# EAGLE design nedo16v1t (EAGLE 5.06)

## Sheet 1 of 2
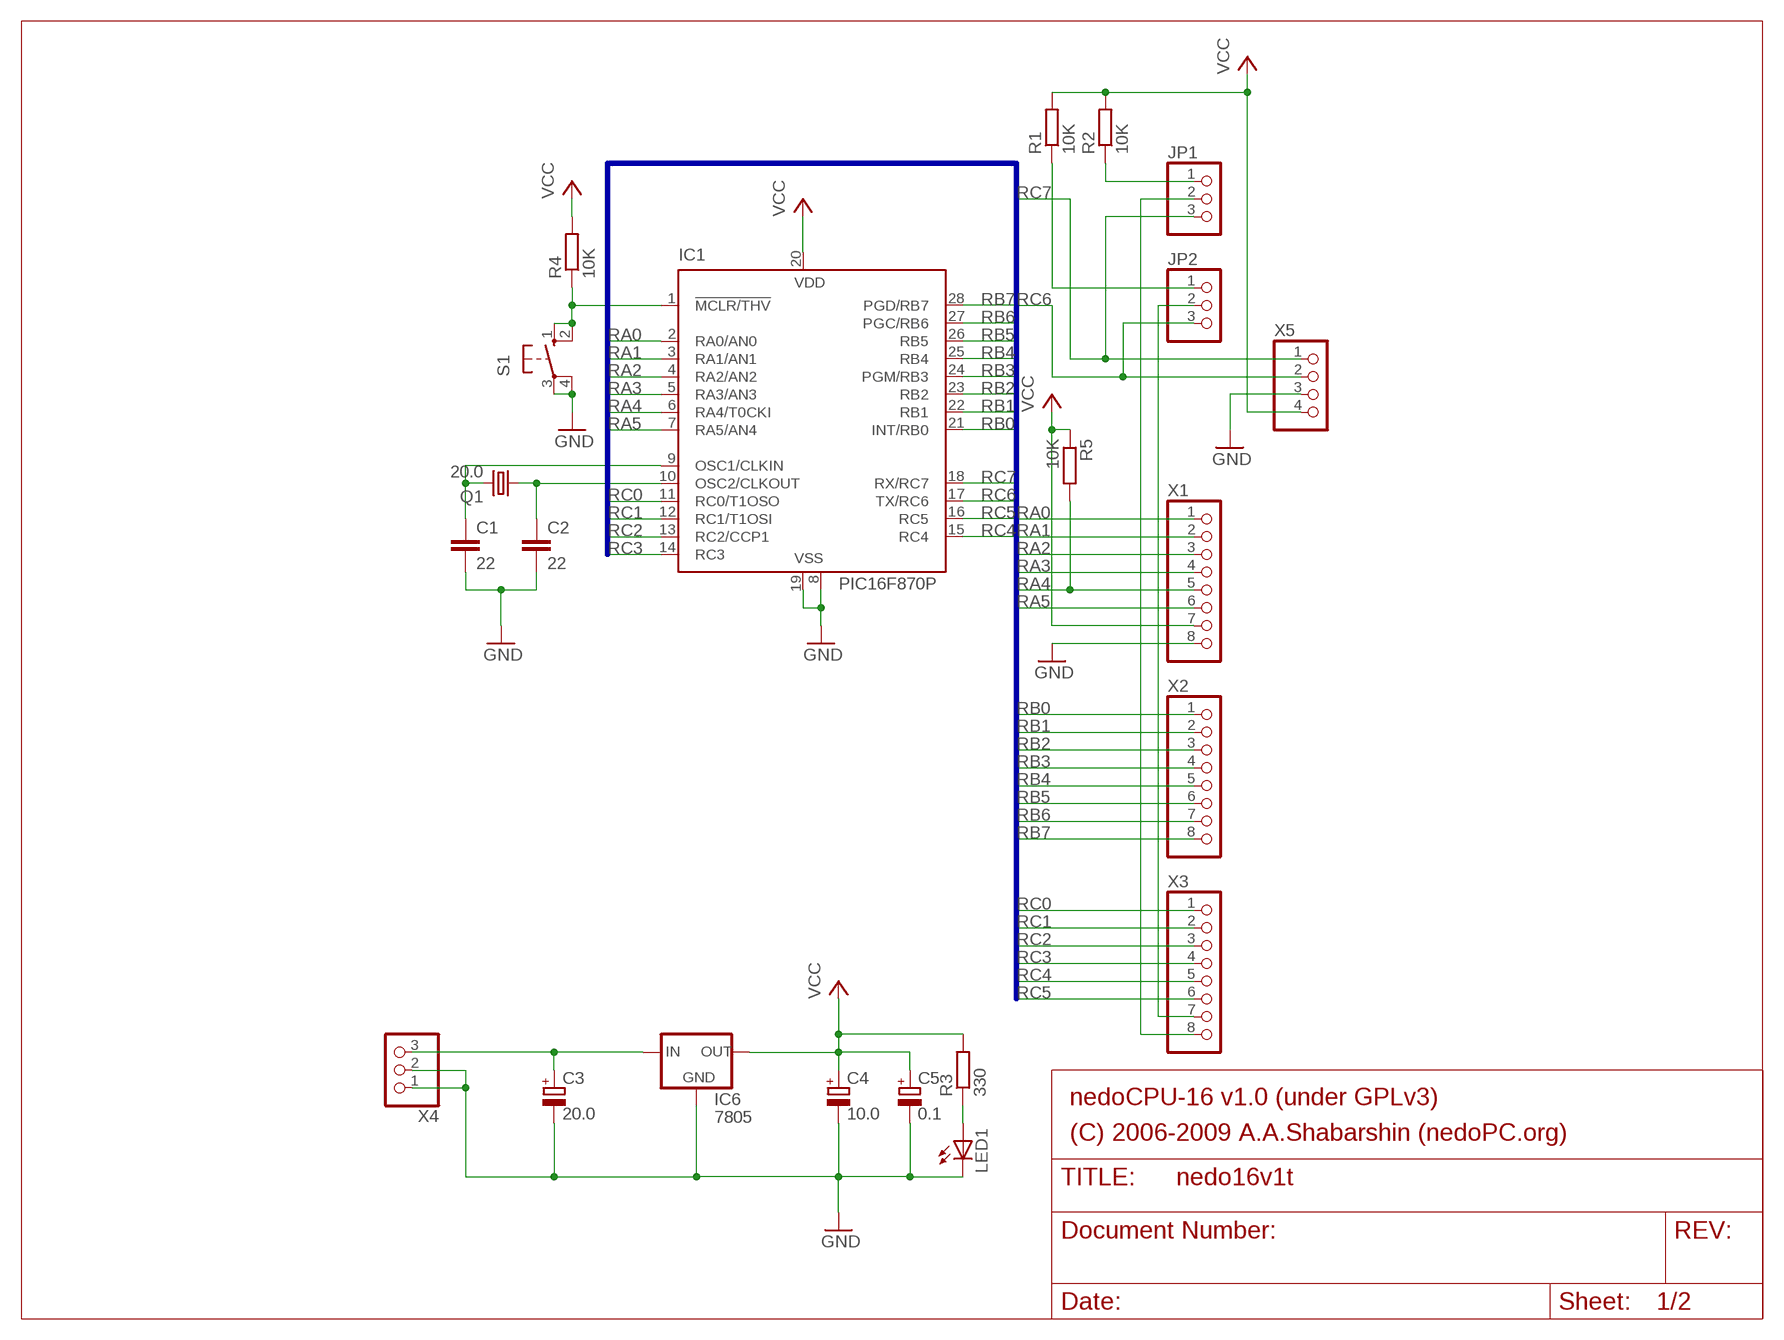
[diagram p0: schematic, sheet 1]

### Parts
C1  22  C-EU025-024X044  [C025-024X044]
C2  22  C-EU025-024X044  [C025-024X044]
C3  20.0  CPOL-EUE5-6  [E5-6]
C4  10.0  CPOL-EUE2.5-6  [E2,5-6]
C5  0.1  CPOL-EUB45181A  [B45181A]
IC1  PIC16F870P  [DIL28-3]
IC6  7805  78XXS  [78XXS]
JP1  PINHD-1X3  [1X03]
JP2  PINHD-1X3  [1X03]
LED1  LED5MM  [LED5MM]
Q1  20.0  CRYSTALHC49U-V  [HC49U-V]
R1  10K  R-EU_0204/7  [0204/7]
R2  10K  R-EU_0204/7  [0204/7]
R3  330  R-EU_0204/7  [0204/7]
R4  10K  R-EU_0204/7  [0204/7]
R5  10K  R-EU_0207/7  [0207/7]
S1  10-XX  [B3F-10XX]
X1  PINHD-1X8  [1X08]
X2  PINHD-1X8  [1X08]
X3  PINHD-1X8  [1X08]
X4  PINHD-1X3  [1X03]
X5  PINHD-1X4  [1X04]

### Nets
GND: C1.2 C2.2 C3.- C4.- C5.- IC1.8(VSS) IC1.19(VSS) IC6.GND LED1.K(C) S1.3(P) S1.4(P1) X1.8 X4.1 X4.2 X5.3 ; also sheet 2
N$3: IC1.1(!MCLR/THV) R4.1 S1.1(S) S1.2(S1)
N$4: JP1.1 R2.1
N$5: JP2.1 R1.1
N$7: LED1.A R3.1
N$10: C2.1 IC1.10(OSC2/CLKOUT) Q1.1
N$14: C3.+ IC6.IN X4.3
N$16: C1.1 IC1.9(OSC1/CLKIN) Q1.2
RA0: IC1.2(RA0/AN0) X1.1 ; also sheet 2
RA1: IC1.3(RA1/AN1) X1.2 ; also sheet 2
RA2: IC1.4(RA2/AN2) X1.3 ; also sheet 2
RA3: IC1.5(RA3/AN3) X1.4 ; also sheet 2
RA4: IC1.6(RA4/T0CKI) R5.2 X1.5 ; also sheet 2
RA5: IC1.7(RA5/AN4) X1.6 ; also sheet 2
RB0: IC1.21(INT/RB0) X2.1 ; also sheet 2
RB1: IC1.22(RB1) X2.2 ; also sheet 2
RB2: IC1.23(RB2) X2.3 ; also sheet 2
RB3: IC1.24(PGM/RB3) X2.4 ; also sheet 2
RB4: IC1.25(RB4) X2.5 ; also sheet 2
RB5: IC1.26(RB5) X2.6 ; also sheet 2
RB6: IC1.27(PGC/RB6) X2.7 ; also sheet 2
RB7: IC1.28(PGD/RB7) X2.8 ; also sheet 2
RC0: IC1.11(RC0/T1OSO) X3.1 ; also sheet 2
RC1: IC1.12(RC1/T1OSI) X3.2 ; also sheet 2
RC2: IC1.13(RC2/CCP1) X3.3 ; also sheet 2
RC3: IC1.14(RC3) X3.4 ; also sheet 2
RC4: IC1.15(RC4) X3.5 ; also sheet 2
RC5: IC1.16(RC5) X3.6 ; also sheet 2
RC6: IC1.17(TX/RC6) JP2.3 X5.2
RC7: IC1.18(RX/RC7) JP1.3 X5.1
RX: JP1.2 X3.8 ; also sheet 2
TX: JP2.2 X3.7 ; also sheet 2
VCC: C4.+ C5.+ IC1.20(VDD) IC6.OUT R1.2 R2.2 R3.2 R4.2 R5.1 X1.7 X5.4 ; also sheet 2

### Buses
RA[0..5],RB[0..7],RC[0..7]

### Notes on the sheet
- nedoCPU-16 v1.0 (under GPLv3)
- (C) 2006-2009 A.A.Shabarshin (nedoPC.org)

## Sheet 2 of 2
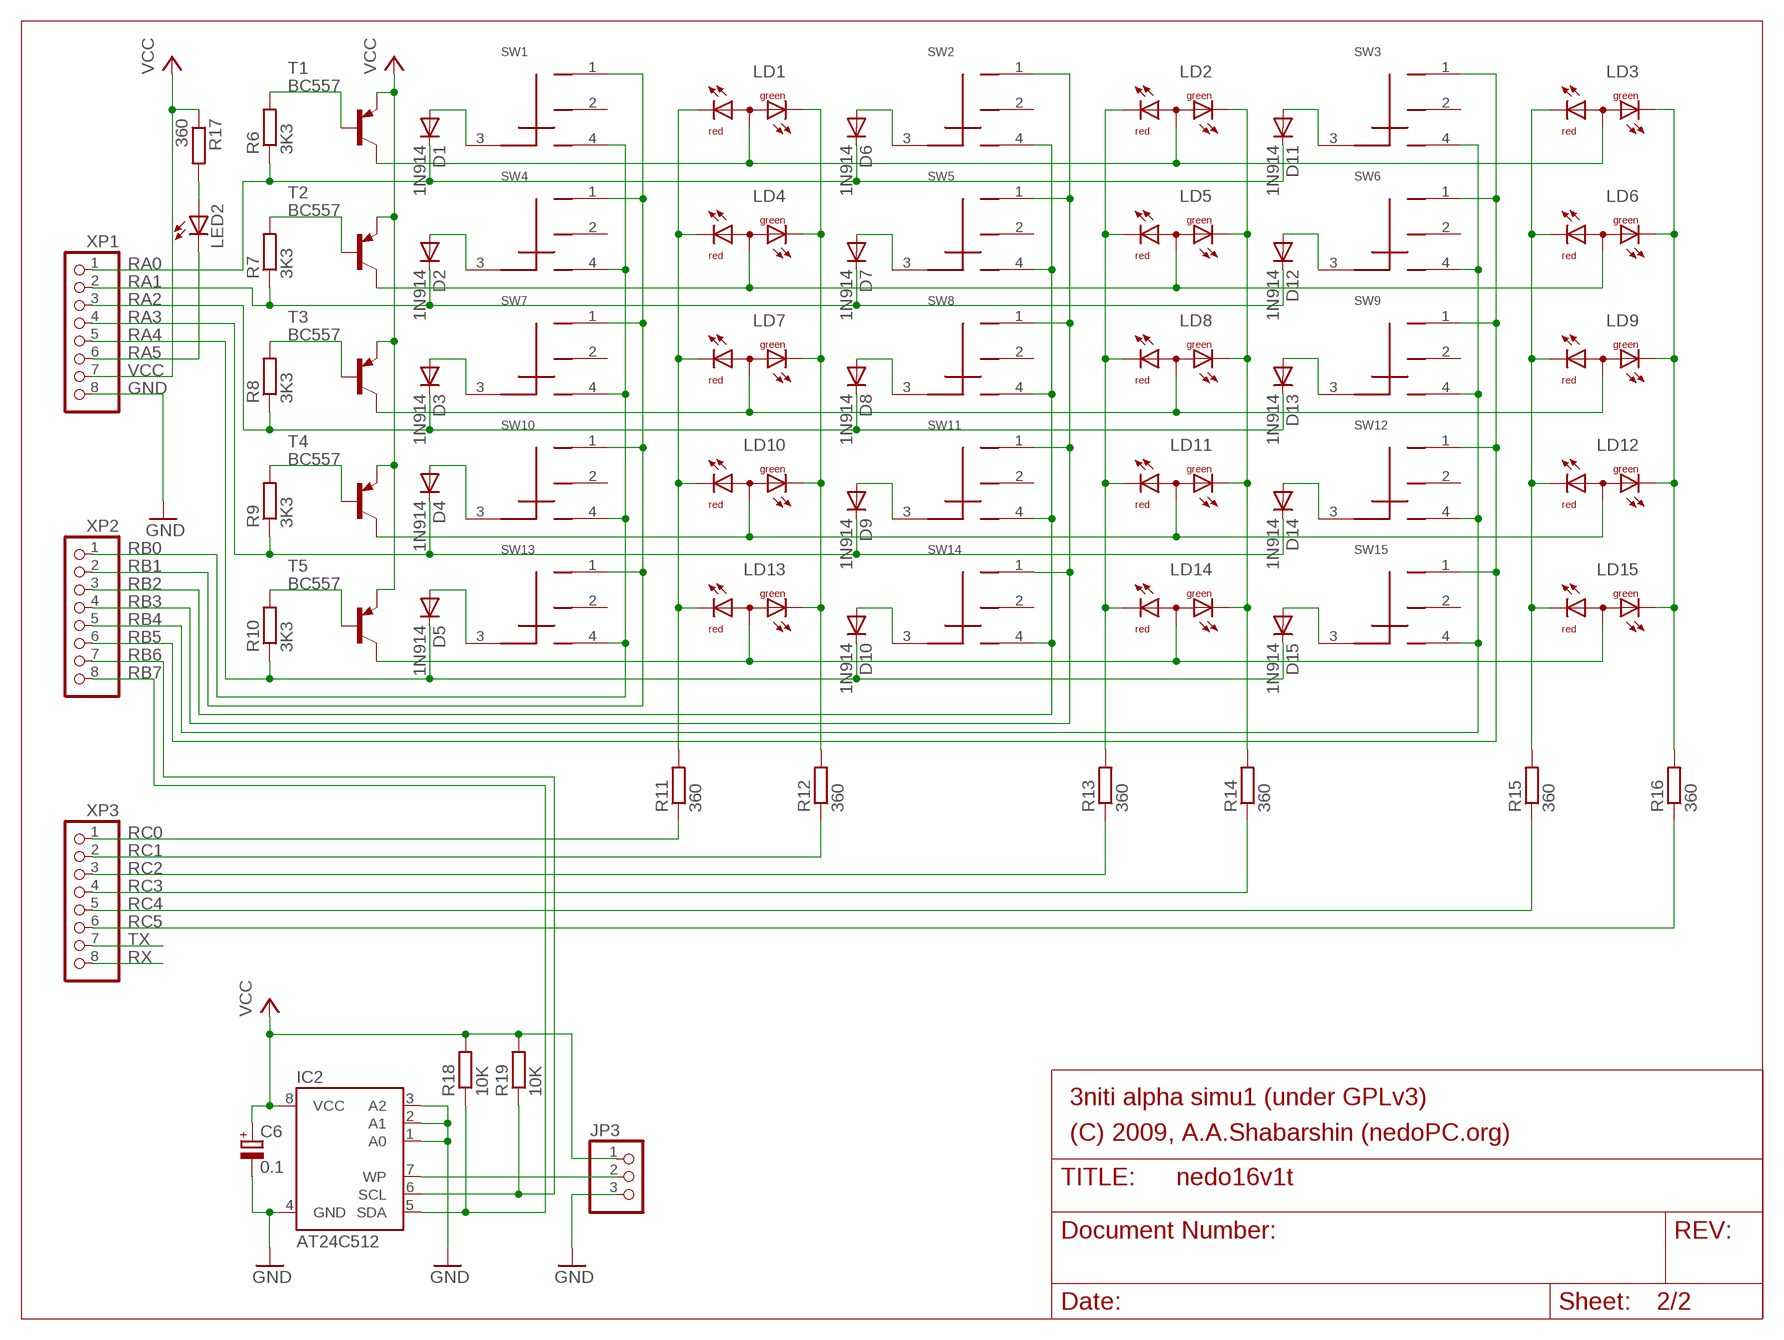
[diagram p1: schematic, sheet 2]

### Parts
C6  0.1  CPOL-EUB45181A  [B45181A]
D1  1N914  1N4148DO35-7  [DO35-7]
D2  1N914  1N4148DO35-7  [DO35-7]
D3  1N914  1N4148DO35-7  [DO35-7]
D4  1N914  1N4148DO35-7  [DO35-7]
D5  1N914  1N4148DO35-7  [DO35-7]
D6  1N914  1N4148DO35-7  [DO35-7]
D7  1N914  1N4148DO35-7  [DO35-7]
D8  1N914  1N4148DO35-7  [DO35-7]
D9  1N914  1N4148DO35-7  [DO35-7]
D10  1N914  1N4148DO35-7  [DO35-7]
D11  1N914  1N4148DO35-7  [DO35-7]
D12  1N914  1N4148DO35-7  [DO35-7]
D13  1N914  1N4148DO35-7  [DO35-7]
D14  1N914  1N4148DO35-7  [DO35-7]
D15  1N914  1N4148DO35-7  [DO35-7]
IC2  AT24C512  AT24CP  [DIL08]
JP3  PINHD-1X3  [1X03]
LD1  DUOLED-RG-A  [DUOLED-A-5MM]
LD2  DUOLED-RG-A  [DUOLED-A-5MM]
LD3  DUOLED-RG-A  [DUOLED-A-5MM]
LD4  DUOLED-RG-A  [DUOLED-A-5MM]
LD5  DUOLED-RG-A  [DUOLED-A-5MM]
LD6  DUOLED-RG-A  [DUOLED-A-5MM]
LD7  DUOLED-RG-A  [DUOLED-A-5MM]
LD8  DUOLED-RG-A  [DUOLED-A-5MM]
LD9  DUOLED-RG-A  [DUOLED-A-5MM]
LD10  DUOLED-RG-A  [DUOLED-A-5MM]
LD11  DUOLED-RG-A  [DUOLED-A-5MM]
LD12  DUOLED-RG-A  [DUOLED-A-5MM]
LD13  DUOLED-RG-A  [DUOLED-A-5MM]
LD14  DUOLED-RG-A  [DUOLED-A-5MM]
LD15  DUOLED-RG-A  [DUOLED-A-5MM]
LED2  LED3MM  [LED3MM]
R6  3K3  R-EU_0204/2V  [0204V]
R7  3K3  R-EU_0204/2V  [0204V]
R8  3K3  R-EU_0204/2V  [0204V]
R9  3K3  R-EU_0204/2V  [0204V]
R10  3K3  R-EU_0204/2V  [0204V]
R11  360  R-EU_0204/2V  [0204V]
R12  360  R-EU_0204/2V  [0204V]
R13  360  R-EU_0204/2V  [0204V]
R14  360  R-EU_0204/2V  [0204V]
R15  360  R-EU_0204/2V  [0204V]
R16  360  R-EU_0204/2V  [0204V]
R17  360  R-EU_0207/2V  [0207/2V]
R18  10K  R-EU_0207/2V  [0207/2V]
R19  10K  R-EU_0207/2V  [0207/2V]
SW1  SP3T  [SP3T]
SW2  SP3T  [SP3T]
SW3  SP3T  [SP3T]
SW4  SP3T  [SP3T]
SW5  SP3T  [SP3T]
SW6  SP3T  [SP3T]
SW7  SP3T  [SP3T]
SW8  SP3T  [SP3T]
SW9  SP3T  [SP3T]
SW10  SP3T  [SP3T]
SW11  SP3T  [SP3T]
SW12  SP3T  [SP3T]
SW13  SP3T  [SP3T]
SW14  SP3T  [SP3T]
SW15  SP3T  [SP3T]
T1  BC557  BC557A-PNP-TO92-EBC  [TO92-EBC]
T2  BC557  BC557A-PNP-TO92-EBC  [TO92-EBC]
T3  BC557  BC557A-PNP-TO92-EBC  [TO92-EBC]
T4  BC557  BC557A-PNP-TO92-EBC  [TO92-EBC]
T5  BC557  BC557A-PNP-TO92-EBC  [TO92-EBC]
XP1  PINHD-1X8  [1X08]
XP2  PINHD-1X8  [1X08]
XP3  PINHD-1X8  [1X08]

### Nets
GND: C6.- IC2.1(A0) IC2.2(A1) IC2.3(A2) IC2.4(GND) JP3.3 XP1.8 ; also sheet 1
N$1: LD1.CR LD4.CR LD7.CR LD10.CR LD13.CR R11.2
N$2: LD1.A LD2.A LD3.A T1.C
N$6: R6.2 T1.B
N$8: LD1.CX(CG) LD4.CX(CG) LD7.CX(CG) LD10.CX(CG) LD13.CX(CG) R12.2
N$9: LD4.A LD5.A LD6.A T2.C
N$11: R7.2 T2.B
N$12: R8.2 T3.B
N$13: R9.2 T4.B
N$15: R10.2 T5.B
N$17: LD7.A LD8.A LD9.A T3.C
N$18: LD10.A LD11.A LD12.A T4.C
N$19: LD13.A LD14.A LD15.A T5.C
N$20: LD2.CR LD5.CR LD8.CR LD11.CR LD14.CR R13.2
N$21: LD2.CX(CG) LD5.CX(CG) LD8.CX(CG) LD11.CX(CG) LD14.CX(CG) R14.2
N$22: LD3.CR LD6.CR LD9.CR LD12.CR LD15.CR R15.2
N$23: LD3.CX(CG) LD6.CX(CG) LD9.CX(CG) LD12.CX(CG) LD15.CX(CG) R16.2
N$24: LED2.A R17.2
N$25: D1.A SW1.3
N$26: D2.A SW4.3
N$27: D3.A SW7.3
N$28: D4.A SW10.3
N$29: D5.A SW13.3
N$30: D15.A SW15.3
N$31: D14.A SW12.3
N$32: D13.A SW9.3
N$33: D12.A SW6.3
N$34: D11.A SW3.3
N$35: D7.A SW5.3
N$36: D8.A SW8.3
N$37: D9.A SW11.3
N$38: D10.A SW14.3
N$39: IC2.7(WP) JP3.2
N$40: D6.A SW2.3
RA0: D1.C D6.C D11.C R6.1 XP1.1 ; also sheet 1
RA1: D2.C D7.C D12.C R7.1 XP1.2 ; also sheet 1
RA2: D3.C D8.C D13.C R8.1 XP1.3 ; also sheet 1
RA3: D4.C D9.C D14.C R9.1 XP1.4 ; also sheet 1
RA4: D5.C D10.C D15.C R10.1 XP1.5 ; also sheet 1
RA5: LED2.K(C) XP1.6 ; also sheet 1
RB0: SW1.4 SW4.4 SW7.4 SW10.4 SW13.4 XP2.1 ; also sheet 1
RB1: SW1.1 SW4.1 SW7.1 SW10.1 SW13.1 XP2.2 ; also sheet 1
RB2: SW2.4 SW5.4 SW8.4 SW11.4 SW14.4 XP2.3 ; also sheet 1
RB3: SW2.1 SW5.1 SW8.1 SW11.1 SW14.1 XP2.4 ; also sheet 1
RB4: SW3.4 SW6.4 SW9.4 SW12.4 SW15.4 XP2.5 ; also sheet 1
RB5: SW3.1 SW6.1 SW9.1 SW12.1 SW15.1 XP2.6 ; also sheet 1
RB6: IC2.6(SCL) R19.1 XP2.7 ; also sheet 1
RB7: IC2.5(SDA) R18.1 XP2.8 ; also sheet 1
RC0: R11.1 XP3.1 ; also sheet 1
RC1: R12.1 XP3.2 ; also sheet 1
RC2: R13.1 XP3.3 ; also sheet 1
RC3: R14.1 XP3.4 ; also sheet 1
RC4: R15.1 XP3.5 ; also sheet 1
RC5: R16.1 XP3.6 ; also sheet 1
RX: XP3.8 ; also sheet 1
TX: XP3.7 ; also sheet 1
VCC: C6.+ IC2.8(VCC) JP3.1 R17.1 R18.2 R19.2 T1.E T2.E T3.E T4.E T5.E XP1.7 ; also sheet 1
Unconnected: SW1.2 SW2.2 SW3.2 SW4.2 SW5.2 SW6.2 SW7.2 SW8.2 SW9.2 SW10.2 SW11.2 SW12.2 SW13.2 SW14.2 SW15.2

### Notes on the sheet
- 3niti alpha simu1 (under GPLv3)
- (C) 2009, A.A.Shabarshin (nedoPC.org)

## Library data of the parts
C1 C2 = rcl:C-EU: CAPACITOR, European symbol
C3-C6 = rcl:CPOL-EU: POLARIZED CAPACITOR, European symbol
D1-D15 = diode:1N4148: DIODE
IC1 = microchip:PIC16*870: MICROCONTROLLER flash type
IC2 = atmel:AT24C*: 2-wire serial EEPROM
IC6 = v-reg:78XXS: VOLTAGE REGULATOR
JP1-JP3 X4 = pinhead:PINHD-1X3: PIN HEADER
LD1-LD15 = led:DUOLED-RG-A: DUO LED 2 colors (red/green), 5 mm, round, common Anode www.ligitek.com or other producers.
LED1 LED2 = led:LED: LED
Q1 = crystal:CRYSTAL: CRYSTAL
R1-R19 = rcl:R-EU_: RESISTOR, European symbol
S1 = switch-omron:10-XX: OMRON SWITCH
SW1-SW15 = shaos560:SP3T: SP3T On-On-On Slide Switch (Mouser 611-OS103012MU2QP1)
T1-T5 = transistor:*-PNP-: PNP Transistror
X1-X3 XP1-XP3 = pinhead:PINHD-1X8: PIN HEADER
X5 = pinhead:PINHD-1X4: PIN HEADER

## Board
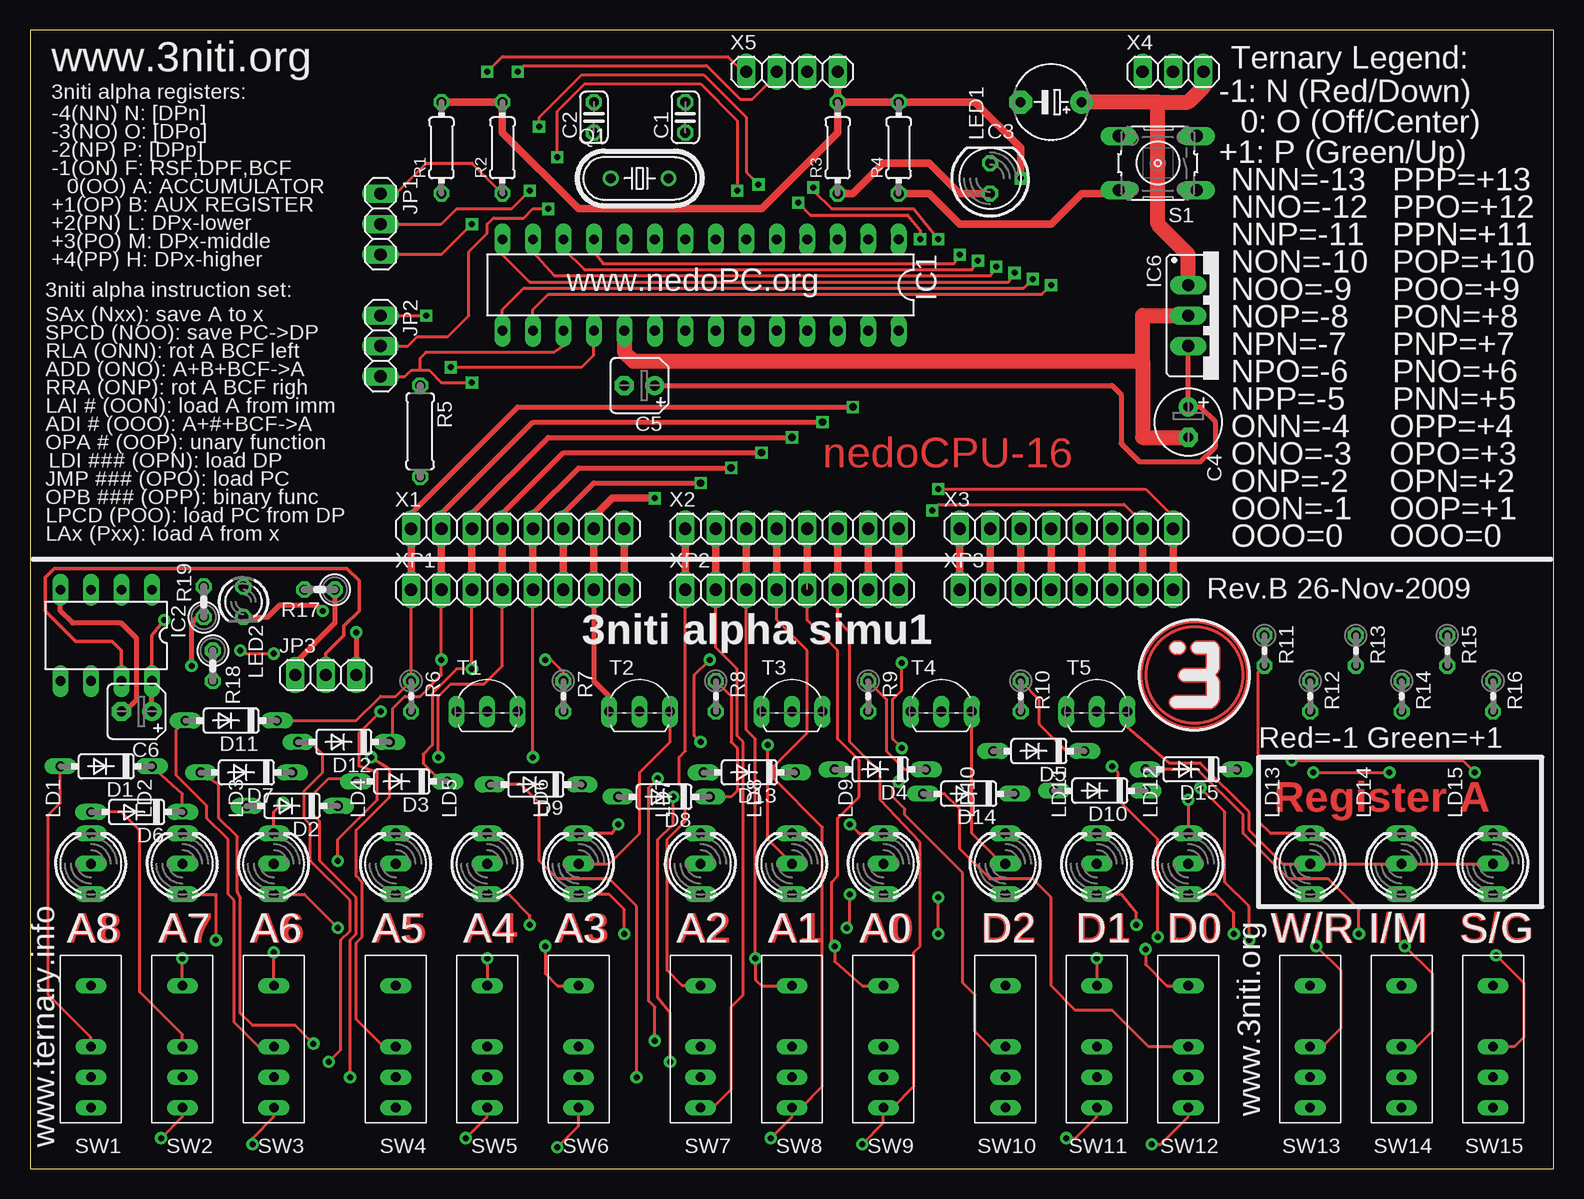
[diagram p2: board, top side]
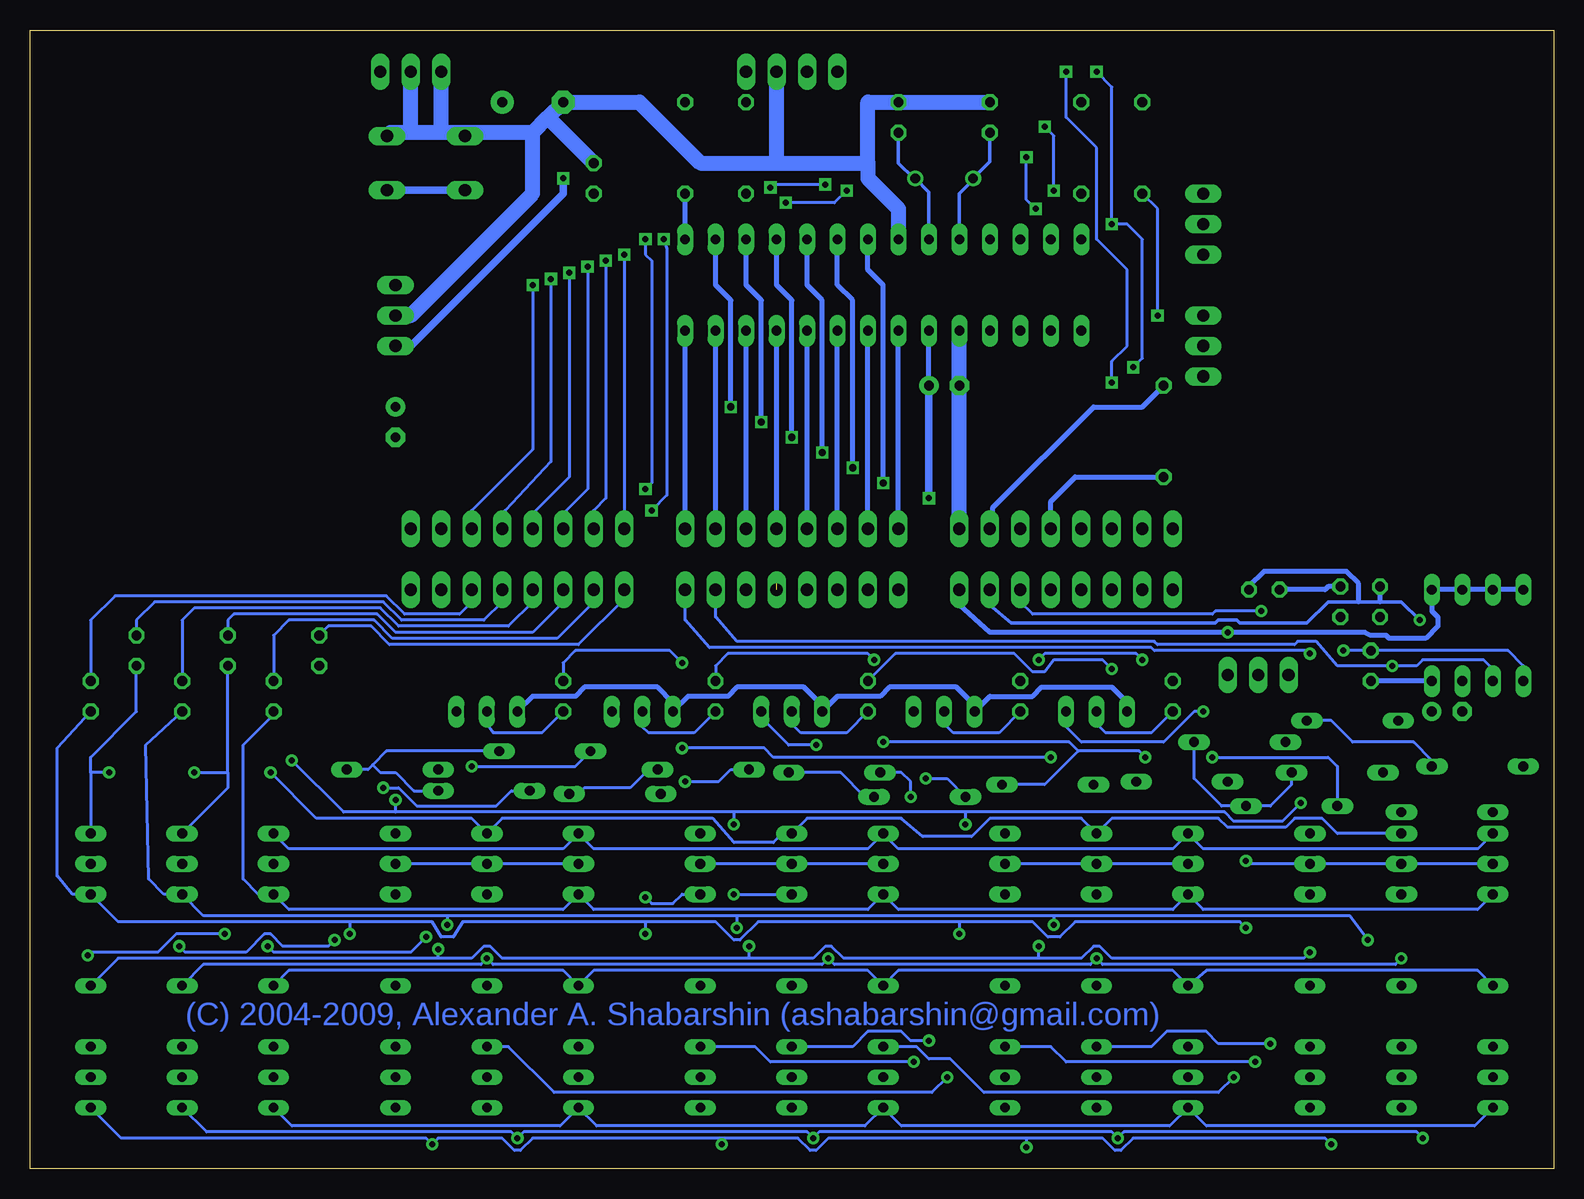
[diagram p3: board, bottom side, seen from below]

Size 126.98 x 94.92 mm. Coordinates in mm from the lower left corner, seen from the top.
Outline: 0,0 126.98,0 126.98,94.92 0,94.92 0,0
Copper layers (1*16): Top 0.035mm / dielectric 1.5mm / Bottom 0.035mm
Design rules "default *": minimum track width 10mil, minimum drill 16mil, track to track 10mil, track to pad 10mil, pad to pad 10mil, via to via 10mil, smd to smd 10mil, copper to edge 40mil, drill to drill 8mil, minimum pad ring 10mil, minimum via ring 8mil, stop-mask expansion 4mil, vias tented up to drill 0mil, thermal gap 10mil

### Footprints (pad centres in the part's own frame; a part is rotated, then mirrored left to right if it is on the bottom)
C025-024X044 = drill 0.813 octagon: 1 -1.27,0; 2 1.27,0
E5-6 = drill 0.813 pad 1.905 round: + -2.54,0 | drill 0.813 pad 1.905 octagon: - 2.54,0
E2,5-6 = drill 0.813 pad 1.6 round: + -1.27,0 | drill 0.813 pad 1.6 octagon: - 1.27,0
B45181A = drill 0.813 pad 1.6 round: + -1.27,0 | drill 0.813 pad 1.6 octagon: - 1.27,0
DO35-7 = drill 0.813 long: A 3.81,0; C -3.81,0
DIL28-3 = drill 0.813 long: 1 -16.51,-3.81; 2 -13.97,-3.81; 3 -11.43,-3.81; 4 -8.89,-3.81; 5 -6.35,-3.81; 6 -3.81,-3.81; 7 -1.27,-3.81; 8 1.27,-3.81; 9 3.81,-3.81; 10 6.35,-3.81; 11 8.89,-3.81; 12 11.43,-3.81; 13 13.97,-3.81; 14 16.51,-3.81; 15 16.51,3.81; 16 13.97,3.81; 17 11.43,3.81; 18 8.89,3.81; 19 6.35,3.81; 20 3.81,3.81; 21 1.27,3.81; 22 -1.27,3.81; 23 -3.81,3.81; 24 -6.35,3.81; 25 -8.89,3.81; 26 -11.43,3.81; 27 -13.97,3.81; 28 -16.51,3.81
DIL08 = drill 0.813 long: 1 -3.81,-3.81; 2 -1.27,-3.81; 3 1.27,-3.81; 4 3.81,-3.81; 5 3.81,3.81; 6 1.27,3.81; 7 -1.27,3.81; 8 -3.81,3.81
78XXS = drill 1.016 long: GND 0,-2.54; IN -2.54,-2.54; OUT 2.54,-2.54
1X03 = drill 1.016 long: 1 -2.54,0; 2 0,0; 3 2.54,0
DUOLED-A-5MM = drill 0.813 long: A 0,0; CR 2.54,0; CX -2.54,0
LED5MM = drill 0.813 octagon: A -1.27,0; K 1.27,0
LED3MM = drill 0.813 octagon: A -1.27,0; K 1.27,0
HC49U-V = drill 0.813 round: 1 -2.413,0; 2 2.413,0
0204/7 = drill 0.813 octagon: 1 -3.81,0; 2 3.81,0
0207/7 = drill 0.813 octagon: 1 -3.81,0; 2 3.81,0
0204V = drill 0.813 octagon: 1 -1.27,0; 2 1.27,0
0207/2V = drill 0.813 octagon: 1 -1.27,0; 2 1.27,0
B3F-10XX = drill 1.016 long: 1 -3.251,2.261; 2 3.251,2.261; 3 -3.251,-2.261; 4 3.251,-2.261
SP3T = drill 0.8 long: 1 0,5.08; 2 0,2.54; 3 0,0; 4 0,-5.08
TO92-EBC = drill 0.813 long: B 0,-1.27; C 2.54,-1.27; E -2.54,-1.27
1X08 = drill 1.016 long: 1 -8.89,0; 2 -6.35,0; 3 -3.81,0; 4 -1.27,0; 5 1.27,0; 6 3.81,0; 7 6.35,0; 8 8.89,0
1X04 = drill 1.016 long: 1 -3.81,0; 2 -1.27,0; 3 1.27,0; 4 3.81,0

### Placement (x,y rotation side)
C1  54.61,87.63 90 top
C2  46.99,87.63 90 top
C3  85.09,88.9 180 top
C4  96.52,62.23 270 top
C5  50.8,65.28 180 top
C6  8.89,38.1 180 top
D1  6.35,33.53 180 top
D2  21.84,30.23 180 top
D3  30.99,32.26 180 top
D4  70.87,33.27 180 top
D5  84.07,34.8 180 top
D6  8.89,29.72 180 top
D7  18.03,33.02 180 top
D8  52.83,30.99 180 top
D9  42.16,32 180 top
D10  89.15,31.5 180 top
D11  16.76,37.34 180 top
D12  26.16,35.56 180 top
D13  59.94,33.02 180 top
D14  78.23,31.24 180 top
D15  96.77,33.27 180 top
IC1  55.88,73.66 180 top
IC2  6.35,44.45 180 top
IC6  99.06,71.12 270 top
JP1  29.21,78.74 270 top
JP2  29.21,68.58 270 top
JP3  24.64,41.15 0 top
LD1  5.08,25.4 90 top
LD2  12.7,25.4 90 top
LD3  20.32,25.4 90 top
LD4  30.48,25.4 90 top
LD5  38.1,25.4 90 top
LD6  45.72,25.4 90 top
LD7  55.88,25.4 90 top
LD8  63.5,25.4 90 top
LD9  71.12,25.4 90 top
LD10  81.28,25.4 90 top
LD11  88.9,25.4 90 top
LD12  96.52,25.4 90 top
LD13  106.68,25.4 90 top
LD14  114.3,25.4 90 top
LD15  121.92,25.4 90 top
LED1  80.01,82.55 90 top
LED2  17.78,47.24 270 top
Q1  50.8,82.55 0 top
R1  34.29,85.09 90 top
R2  39.37,85.09 90 top
R3  67.31,85.09 90 top
R4  72.39,85.09 90 top
R5  32.51,61.47 270 top
R6  31.75,39.37 270 top
R7  44.45,39.37 270 top
R8  57.15,39.37 270 top
R9  69.85,39.37 270 top
R10  82.55,39.37 270 top
R11  102.87,43.18 270 top
R12  106.68,39.37 270 top
R13  110.49,43.18 270 top
R14  114.3,39.37 270 top
R15  118.11,43.18 270 top
R16  121.92,39.37 270 top
R17  24.13,48.26 180 top
R18  15.24,41.91 270 top
R19  14.48,47.24 90 top
S1  93.98,83.82 180 top
SW1  5.08,10.16 180 top
SW2  12.7,10.16 180 top
SW3  20.32,10.16 180 top
SW4  30.48,10.16 180 top
SW5  38.1,10.16 180 top
SW6  45.72,10.16 180 top
SW7  55.88,10.16 180 top
SW8  63.5,10.16 180 top
SW9  71.12,10.16 180 top
SW10  81.28,10.16 180 top
SW11  88.9,10.16 180 top
SW12  96.52,10.16 180 top
SW13  106.68,10.16 180 top
SW14  114.3,10.16 180 top
SW15  121.92,10.16 180 top
T1  38.1,39.37 0 top
T2  50.8,39.37 0 top
T3  63.5,39.37 0 top
T4  75.95,39.37 0 top
T5  88.9,39.37 0 top
X1  40.64,53.34 0 top
X2  63.5,53.34 0 top
X3  86.36,53.34 0 top
X4  95.25,91.44 0 top
X5  63.5,91.44 0 top
XP1  40.64,48.26 0 top
XP2  63.5,48.26 0 top
XP3  86.36,48.26 0 top

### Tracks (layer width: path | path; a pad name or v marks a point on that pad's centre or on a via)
GND  (via drill 0.5 pad 1.02)
  Top 0.406: C6.- 7.87,38.1 8.89,39.12 8.89,44.2 7.62,45.47 3.56,45.47 2.54,46.48 IC2.4 | v27.18,44.7 JP3.3
  Top 0.61: XP1.8 X1.8
  Top 1.27: IC1.19 49.53,68.07 50.29,67.31 92.71,67.31 | 92.71,67.31 92.71,71.12 IC6.GND | 92.71,67.31 92.71,60.96 C4.-
  Bottom 0.406: IC2.4 IC2.3 IC2.2 IC2.1 10.16,46.48 9.65,45.97 9.65,45.21 10.67,44.2 13.72,44.2 13.97,44.45 15.24,44.45 15.75,44.7 v27.18,44.7 46.99,44.7 49.53,46.99 XP1.8
  Bottom 1.27: IC1.19 C5.- X1.8 | 83.82,87.63 C3.- 76.2,88.9 71.12,83.82 64.77,83.82 | 85.09,86.36 90.45,86.36 | 90.45,86.36 S1.4 | 90.45,86.36 92.71,86.36 | 92.71,86.36 95.25,86.36 | 95.25,86.36 96.95,86.36 S1.3 | 95.25,86.36 X4.2 | 92.71,86.36 X4.1 | 83.82,87.63 LED1.K | 85.09,86.36 85.09,81.28 95.25,71.12 IC6.GND | 85.09,86.36 83.82,87.63 | 64.77,83.82 57.15,83.82 | C2.2 C1.2 57.15,88.9 57.15,83.82 | 64.77,83.82 X5.3 | 57.15,83.82 57.15,82.55 54.61,80.01 IC1.8
N$1
  Top 0.254: LD13.CR 103.38,27.94 102.36,28.96 102.36,41.4 R11.2
  Bottom 0.254: LD1.CR 6.35,26.67 29.21,26.67 LD4.CR 31.75,26.67 54.61,26.67 LD7.CR 57.15,26.67 80.01,26.67 LD10.CR 82.55,26.67 105.41,26.67 LD13.CR
N$2  (via drill 0.5 pad 1.02)
  Top 0.254: v25.65,25.65 25.65,27.43 28.96,30.73 28.96,33.02 27.43,33.53 27.43,36.32 v29.21,38.1
  Bottom 0.254: LD1.A LD2.A LD3.A 25.4,25.4 v25.65,25.65 | v29.21,38.1 29.97,38.1 32.51,35.56 39.37,35.56 40.89,37.08 40.89,37.85 T1.C
N$3
  Top 0.61: R4.1 74.93,81.28 77.47,78.74 85.09,78.74 87.63,81.28 90.45,81.28 S1.2
  Bottom 0.406: IC1.1 R4.1
  Bottom 0.61: S1.2 S1.1
N$4
  Top 0.254: JP1.1 30.48,81.28 33.02,83.82 36.83,83.82 R2.1
N$5  (via drill 0.5 pad 1.02)
  Top 0.254: JP2.1 v33.02,71.12
  Bottom 0.254: v33.02,71.12 33.02,80.01 R1.1
N$6
  Bottom 0.254: R6.2 33.53,36.32 37.34,36.32 38.1,37.08 T1.B
N$7
  Top 0.61: R3.1 68.58,81.28 71.12,83.82 74.93,83.82 77.47,81.28 LED1.A
N$8
  Bottom 0.254: LD1.CX 6.35,21.59 29.21,21.59 LD4.CX 31.75,21.59 54.61,21.59 LD7.CX 57.15,21.59 80.01,21.59 LD10.CX 82.55,21.59 105.41,21.59 LD13.CX 107.95,22.86 109.22,24.13 109.22,35.31 106.68,37.85 R12.2
N$9
  Top 0.254: LD6.A 48.26,25.4 50.8,27.94 50.8,33.02 53.34,35.56 T2.C
  Bottom 0.254: LD4.A LD5.A LD6.A
N$10
  Bottom 0.305: C2.1 46.99,83.95 Q1.1 48.39,82.42 49.53,81.28 IC1.10
N$11
  Bottom 0.254: R7.2 46.23,36.32 50.04,36.32 50.8,37.08 T2.B
N$12
  Bottom 0.254: R8.2 58.93,36.32 62.74,36.32 63.5,37.08 T3.B
N$13
  Bottom 0.254: R9.2 71.63,36.32 75.44,36.32 75.95,36.83 T4.B
N$14
  Top 1.27: X4.3 97.79,90.17 96.52,88.9 93.98,88.9 | 93.98,88.9 C3.+ | 93.98,88.9 93.98,78.74 96.52,76.2 IC6.IN
N$15
  Bottom 0.254: R10.2 84.33,36.32 88.39,36.32 88.9,37.08 T5.B
N$16
  Bottom 0.305: IC1.9 52.07,81.41 Q1.2 53.34,82.55 54.61,83.82 C1.1
N$17  (via drill 0.5 pad 1.02)
  Top 0.254: LD8.A 61.47,27.43 v61.47,35.31
  Bottom 0.254: LD7.A LD8.A LD9.A | v61.47,35.31 63.75,35.31 66.04,37.59 T3.C
N$18
  Top 0.254: LD10.A 81.03,25.4 78.49,27.94 T4.C
  Bottom 0.254: LD10.A LD11.A LD12.A
N$19
  Top 0.254: T5.C 91.44,36.83 93.47,35.05 95,33.78 97.54,33.78 101.6,29.72 101.6,28.19 104.39,25.4 LD13.A LD14.A LD15.A
N$20  (via drill 0.5 pad 1.02)
  Top 0.254: v106.93,33.02 v113.28,33.02
  Bottom 0.254: 110.49,33.02 110.49,31.75 LD14.CR | 110.49,33.02 R13.2 | LD2.CR 18.03,27.94 19.3,29.21 21.59,29.21 22.35,28.45 27.18,28.45 27.94,29.21 36.83,29.21 LD5.CR 39.37,29.21 46.99,29.21 48.51,27.69 52.58,27.69 54.36,29.21 62.23,29.21 LD8.CR 64.26,27.94 65.02,27.18 68.33,27.18 70.1,29.21 87.63,29.21 LD11.CR 90.17,29.21 103.12,29.21 v106.93,33.02 | v113.28,33.02 110.49,33.02
N$21  (via drill 0.5 pad 1.02)
  Top 0.254: LD2.CX 15.49,22.86 v15.49,19.05 | LD5.CX 39.88,22.86 41.66,21.08 v41.66,20.32 | v68.33,22.86 68.33,20.32 v68.07,20.07 | LD11.CX 90.93,22.86 92.2,21.34 v92.2,20.32
  Bottom 0.254: v15.49,19.05 17.02,21.08 41.66,21.08 | 41.66,21.08 68.07,21.08 | 68.07,21.08 92.2,21.08 | 92.2,21.08 112.52,21.08 LD14.CX 115.82,22.86 117.09,24.13 117.35,35.31 R14.2 | 41.66,21.08 v41.66,20.32 | v68.33,22.86 LD8.CX | 68.07,21.08 v68.07,20.07 | 92.2,21.08 v92.2,20.32
N$22  (via drill 0.5 pad 1.02)
  Top 0.254: LD3.CR 20.32,29.72 v21.08,30.48 | v105.16,34.04 119.38,34.04 v120.4,33.02 | v96.52,30.73 LD12.CR | LD9.CR 69.09,27.94 v68.33,28.7 | LD6.CR 48.51,27.94 v49.02,28.7
  Bottom 0.254: R15.2 118.11,38.1 121.92,34.29 121.92,33.02 | 121.92,33.02 LD15.CR | v21.08,30.48 22.61,28.96 26.67,28.96 27.43,29.72 49.02,29.72 | 49.02,29.72 68.33,29.72 | 96.52,29.72 100.84,29.72 v105.16,34.04 | v120.4,33.02 121.92,33.02 | 96.52,29.72 v96.52,30.73 | 68.33,29.72 v68.33,28.7 | 68.33,29.72 96.52,29.72 | 49.02,29.72 v49.02,28.7
N$23  (via drill 0.5 pad 1.02)
  Top 0.254: LD3.CX 22.86,22.86 v25.65,20.07 | LD6.CX 48.26,22.86 49.53,21.59 v49.53,19.56 | v75.69,19.56 v75.69,22.61 | LD12.CX 98.81,22.86 100.33,21.34 v100.33,19.56
  Bottom 0.254: v25.65,20.07 26.16,20.57 39.88,20.57 41.15,19.3 42.16,19.3 43.43,20.57 49.53,20.57 | 49.53,20.57 66.29,20.57 67.82,19.05 68.33,19.05 69.85,20.57 75.69,20.57 | 75.69,20.57 90.93,20.57 91.69,19.3 92.71,19.3 93.47,20.57 100.33,20.57 | 100.33,20.57 119.63,20.57 LD15.CX 123.44,22.86 124.71,24.38 124.71,35.05 R16.2 | 49.53,20.57 v49.53,19.56 | LD9.CX 72.64,22.86 73.41,22.1 75.18,22.1 v75.69,22.61 | 75.69,20.57 v75.69,19.56 | 100.33,20.57 v100.33,19.56
N$24
  Bottom 0.406: LED2.A 18.8,48.51 19.05,48.26 R17.2
N$25
  Top 0.254: SW1.3 5.08,10.92 1.52,14.48 1.52,29.46 2.54,30.48 D1.A
N$26  (via drill 0.5 pad 1.02)
  Top 0.254: SW4.3 29.46,10.16 27.18,12.45 27.18,18.8 27.69,19.3 27.69,23.88 27.18,24.38 27.18,28.19 29.97,30.99 29.97,33.27 v28.45,34.29
  Bottom 0.254: v28.45,34.29 18.8,34.29 18.03,33.53 D2.A
N$27  (via drill 0.5 pad 1.02)
  Top 0.254: v26.67,7.62 26.67,19.05 27.18,19.56 27.18,22.61 24.13,25.65 24.13,28.96 23.37,29.72 23.37,30.99 24.89,32.51 26.92,32.51 D3.A
  Bottom 0.254: SW7.3 53.09,10.16 52.07,9.14 50.29,9.14 47.5,6.35 27.94,6.35 v26.67,7.62
N$28  (via drill 0.5 pad 1.02)
  Top 0.254: SW10.3 80.01,10.16 78.74,11.43 78.74,14.48 77.72,15.49 77.72,24.64 72.9,29.46 72.9,29.97 71.88,30.99 71.88,31.75 v72.39,32.26
  Bottom 0.254: v72.39,32.26 69.6,32.26 68.58,33.27 D4.A
N$29  (via drill 0.5 pad 1.02)
  Top 0.254: SW13.3 107.7,10.16 109.22,11.68 109.22,16.51 v107.19,18.54 | v93.98,19.3 93.98,27.43 90.68,30.73 90.68,33.02 v90.17,33.53
  Bottom 0.254: v107.19,18.54 106.68,18.03 95.25,18.03 v93.98,19.3 | v90.17,33.53 81.53,33.53 D5.A
N$30  (via drill 0.5 pad 1.02)
  Top 0.254: SW15.3 123.7,10.16 124.46,10.92 124.46,15.49 v122.17,17.78 | v110.74,19.56 110.74,21.59 108.2,24.13 104.9,24.13 101.09,27.94 101.09,29.46 97.28,33.27 D15.A
  Bottom 0.254: v122.17,17.78 121.92,18.03 116.33,18.03 114.81,19.56 v110.74,19.56
N$31
  Top 0.254: SW12.3 93.22,10.16 90.17,13.21 87.12,13.21 85.09,15.24 85.09,22.61 83.57,24.13 80.01,24.13 77.47,26.67 77.47,29.97 76.2,31.24 D14.A
N$32  (via drill 0.5 pad 1.02)
  Top 0.254: v53.34,8.89 53.34,12.95 52.32,14.22 52.32,27.43 53.59,28.7 v53.59,30.99
  Bottom 0.254: SW9.3 66.55,10.16 65.28,8.89 v53.34,8.89 | v53.59,30.99 53.59,32.26 54.36,33.02 D13.A
N$33  (via drill 0.5 pad 1.02)
  Top 0.254: v24.89,8.89 25.91,9.91 25.91,19.05 26.67,19.81 26.67,22.35 23.37,25.65 23.37,28.7 22.86,29.21 22.86,31.5 24.38,33.02 24.38,34.54 23.37,35.56 D12.A
  Bottom 0.254: SW6.3 41.91,10.16 40.64,8.89 v24.89,8.89
N$34
  Top 0.254: SW3.3 19.05,10.16 17.02,12.19 17.02,22.35 16.51,22.86 16.51,27.43 14.73,29.21 14.73,30.23 12.19,32.77 12.19,36.58 D11.A
N$35  (via drill 0.5 pad 1.02)
  Top 0.254: v23.62,10.41 22.1,11.94 18.54,11.94 17.53,12.95 17.53,22.61 17.27,23.11 17.27,27.69 15.75,29.21 15.75,32 D7.A
  Bottom 0.254: SW5.3 33.53,10.16 32.26,11.43 28.96,11.43 27.94,10.41 v23.62,10.41
N$36  (via drill 0.5 pad 1.02)
  Top 0.254: v52.07,10.67 52.07,13.46 51.56,13.97 51.56,31.75 v52.32,32.51
  Bottom 0.254: SW8.3 58.42,10.16 57.15,11.43 54.36,11.43 53.59,10.67 v52.07,10.67 | v52.32,32.51 50.55,32.51 D8.A
N$37  (via drill 0.5 pad 1.02)
  Top 0.254: v50.55,7.62 50.55,21.84 48.26,24.13 43.94,24.13 42.42,25.65 42.42,30.48 40.89,32 D9.A
  Bottom 0.254: SW11.3 87.12,10.16 83.31,6.35 51.82,6.35 v50.55,7.62
N$38  (via drill 0.5 pad 1.02)
  Top 0.254: SW14.3 115.57,10.16 116.84,11.43 116.84,16.26 v114.55,18.54 | v101.6,19.05 101.6,21.84 99.57,23.88 99.57,29.72 v97.54,31.75
  Bottom 0.254: v114.55,18.54 114.05,18.03 108.97,18.03 107.44,19.56 106.93,19.56 105.92,18.54 102.11,18.54 v101.6,19.05 | v97.54,31.75 96.27,31.75 94.74,30.23 88.14,30.23 86.87,31.5 D10.A
N$39
  Top 0.305: IC2.7 7.62,43.18 6.86,43.94 3.81,43.94 1.27,46.48 1.27,49.28 2.03,50.04 26.42,50.04 27.43,49.02 27.43,46.48 26.16,45.21 26.16,44.45 24.64,42.93 JP3.2
N$40
  Top 0.254: SW2.3 12.7,11.18 9.14,14.73 9.14,28.19 7.62,29.72 D6.A
N$41
  Top 1.27: 97.28,43.43 98.55,43.43 98.55,41.66
N$42
  Top 1.27: 96.27,41.15 98.04,41.15
N$43
  Top 1.27: 98.55,40.64 98.55,39.12 98.3,38.86 95.5,38.86
N$44
  Top 1.27: 95.5,43.43 95.76,43.43
RA0  (via drill 0.6)
  Top 0.254: XP1.1 R6.1 30.48,39.37 29.21,39.37 27.18,37.34 D11.C | D6.C 12.7,31.24 D1.C
  Top 0.406: v68.58,63.5 40.64,63.5 31.75,54.61 X1.1
  Top 0.61: XP1.1 X1.1
  Bottom 0.254: D1.C 10.16,34.04 11.68,35.56 16.76,35.56 18.54,37.34 D11.C
  Bottom 0.406: IC1.2 69.85,73.66 68.58,72.39 v68.58,63.5
RA1  (via drill 0.5 pad 1.02, 0.6)
  Top 0.254: XP1.2 v34.29,42.42 34.29,41.15 32.51,39.37 31.24,39.37 30.23,38.35 30.23,35.81 D12.C | v42.93,42.42 43.43,42.42 44.45,41.4 R7.1
  Top 0.406: v66.04,62.23 41.91,62.23 34.29,54.61 X1.2
  Top 0.61: XP1.2 X1.2
  Bottom 0.254: v34.29,42.42 34.8,42.93 42.42,42.93 v42.93,42.42 | D7.C 21.84,32 23.62,30.23 D2.C 27.69,30.23 29.97,32.51 D12.C
  Bottom 0.406: IC1.3 67.31,73.66 66.04,72.39 v66.04,62.23
RA2  (via drill 0.5 pad 1.02, 0.6)
  Top 0.254: R8.1 58.42,39.37 58.42,35.56 58.93,35.05 58.93,31.5 58.42,30.99 D8.C | XP1.3 v36.83,41.66 35.56,41.66 33.53,39.62 33.53,35.31 32.77,34.54 32.77,33.78 34.29,32.26 D3.C
  Top 0.406: v63.5,60.96 43.18,60.96 36.83,54.61 X1.3
  Top 0.61: XP1.3 X1.3
  Bottom 0.254: R8.1 54.86,42.93 44.96,42.93 43.43,41.4 42.42,41.4 41.66,42.42 37.59,42.42 v36.83,41.66 | D13.C 59.44,33.02 57.4,30.99 D8.C
  Bottom 0.406: IC1.4 64.77,73.66 63.5,72.39 v63.5,60.96
RA3  (via drill 0.5 pad 1.02, 0.6)
  Top 0.254: v56.64,42.42 55.37,41.15 55.37,36.07 v55.88,35.56 | v34.04,34.29 34.04,39.37 35.05,40.39 37.85,40.39 39.37,41.91 39.37,48.77 | R9.1 71.37,39.12 71.37,34.8 72.9,33.27 D4.C
  Top 0.406: v60.96,59.69 44.45,59.69 39.37,54.61 X1.4
  Top 0.61: XP1.4 39.37,48.77 X1.4
  Bottom 0.254: R9.1 69.85,41.91 68.83,42.93 57.15,42.93 v56.64,42.42 | v55.88,35.56 40.39,35.56 39.62,34.8 | 39.62,34.8 34.54,34.8 v34.04,34.29 | D4.C 75.44,33.27 76.96,31.75 80.77,31.75 81.28,31.24 D14.C | D9.C 42.42,32 39.62,34.8
  Bottom 0.406: IC1.5 62.23,73.66 60.96,72.39 v60.96,59.69
RA4  (via drill 0.5 pad 1.02, 0.6)
  Top 0.254: R10.1 84.07,39.12 84.07,37.08 86.36,34.8 D5.C | v72.64,42.16 72.64,39.88 71.88,39.12 71.88,35.81 v72.64,35.05 | v41.91,34.29 XP1.5
  Top 0.406: v58.42,58.42 45.72,58.42 41.91,54.61 X1.5
  Top 0.61: XP1.5 X1.5
  Bottom 0.254: R10.1 82.55,42.16 81.53,43.18 73.66,43.18 v72.64,42.16 | v72.64,35.05 65.79,35.05 65.02,34.29 v41.91,34.29 | D5.C 97.28,34.8 98.42,33.66 | 98.42,33.66 98.81,33.27 D15.C | D10.C 95,31.5 96.52,33.02 97.79,33.02 98.42,33.66
  Bottom 0.406: IC1.6 59.69,73.66 58.42,72.39 v58.42,58.42 | R5.2 39.88,57.66 41.91,55.63 X1.5
RA5  (via drill 0.5 pad 1.02, 0.6)
  Top 0.406: v55.88,57.15 46.99,57.15 44.45,54.61 X1.6 | LED2.K 19.81,45.97 20.83,46.99 23.88,46.99 v24.38,46.48
  Top 0.61: XP1.6 X1.6
  Bottom 0.254: XP1.6 44.45,47.24 43.43,46.23 28.45,46.23 28.19,46.48 v24.38,46.48
  Bottom 0.406: IC1.7 57.15,74.93 55.88,73.66 v55.88,57.15
RB0
  Top 0.254: XP2.1 54.61,34.8 54.1,34.29 54.1,32 54.61,31.5 54.61,28.96 53.09,27.43 53.09,16.51 54.36,15.24 SW7.4
  Top 0.61: XP2.1 X2.1
  Bottom 0.254: SW1.4 6.35,16.51 28.96,16.51 SW4.4 31.75,16.51 54.61,16.51 SW7.4 57.15,16.51 80.01,16.51 SW10.4 82.55,16.51 105.41,16.51 SW13.4
  Bottom 0.406: X2.1 IC1.21
RB1
  Top 0.254: XP2.2 57.15,43.43 58.93,41.66 58.93,36.07 59.44,35.56 59.44,14.48 58.42,13.46 58.42,6.6 56.9,5.08 SW7.1
  Top 0.61: XP2.2 X2.2
  Bottom 0.254: SW1.1 6.6,3.56 28.96,3.56 SW4.1 32,3.56 54.36,3.56 SW7.1 57.4,3.56 79.76,3.56 SW10.1 82.8,3.56 105.16,3.56 SW13.1
  Bottom 0.406: X2.2 IC1.22
RB2  (via drill 0.5 pad 1.02)
  Top 0.254: XP2.3 59.69,36.58 60.45,35.81 v60.45,17.53 60.45,15.75 60.96,15.24 SW8.4 | SW2.4 v12.7,17.53 | v38.1,17.53 SW5.4 | v88.9,17.53 SW11.4
  Top 0.61: XP2.3 X2.3
  Bottom 0.254: v12.7,17.53 13.21,17.02 37.59,17.02 v38.1,17.53 38.61,17.02 59.94,17.02 v60.45,17.53 60.96,17.02 88.39,17.02 v88.9,17.53 89.41,17.02 112.52,17.02 SW14.4
  Bottom 0.406: X2.3 IC1.23
RB3  (via drill 0.5 pad 1.02)
  Top 0.254: SW2.1 12.7,4.32 v10.92,2.54 | v36.32,2.54 38.1,4.32 SW5.1 | v61.72,2.54 63.5,4.32 SW8.1 64.26,5.08 66.04,6.86 66.04,28.45 61.98,32.51 61.98,33.53 64.77,36.32 64.77,43.18 62.23,45.72 XP2.4 | SW11.1 88.9,4.32 87.12,2.54 v86.36,2.54
  Top 0.61: XP2.4 X2.4
  Bottom 0.254: v10.92,2.54 11.43,3.05 35.81,3.05 v36.32,2.54 36.83,3.05 61.21,3.05 v61.72,2.54 62.23,3.05 85.85,3.05 v86.36,2.54 86.87,3.05 112.27,3.05 SW14.1
  Bottom 0.406: X2.4 IC1.24
RB4  (via drill 0.5 pad 1.02)  (1 unrouted)
  Top 0.254: SW3.4 v20.32,18.03 | v42.93,18.54 42.93,16.26 43.94,15.24 SW6.4 | SW9.4 69.34,15.24 67.06,17.27 v67.06,18.54 66.8,18.8 66.8,23.88 67.31,24.38 67.31,29.21 69.09,30.99 69.09,34.04 67.31,35.81 67.31,43.18 64.77,45.72 XP2.5 | SW12.4 94.74,15.24 92.96,17.02 v92.96,18.29
  Top 0.61: 64.77,48.77 X2.5
  Bottom 0.254: v20.32,18.03 20.83,17.53 36.83,17.53 37.85,18.54 38.35,18.54 39.37,17.53 42.93,17.53 | 42.93,17.53 59.18,17.53 60.2,18.54 60.71,18.54 61.72,17.53 67.06,17.53 | 67.06,17.53 87.63,17.53 88.65,18.54 89.15,18.54 90.17,17.53 92.96,17.53 | 92.96,17.53 119.63,17.53 SW15.4 | 42.93,17.53 v42.93,18.54 | 67.06,17.53 v67.06,18.54 | 92.96,17.53 v92.96,18.29
  Bottom 0.406: X2.5 IC1.25
RB5  (via drill 0.5 pad 1.02)
  Top 0.254: v93.47,2.03 94.23,2.03 96.52,4.32 SW12.1 | v18.54,2.03 18.54,2.54 20.32,4.32 SW3.1 | v69.34,2.03 71.12,3.81 SW9.1 71.88,5.08 73.66,6.86 73.66,18.03 74.17,18.54 74.17,27.18 70.87,30.73 70.87,33.02 68.33,35.56 68.33,44.7 67.31,45.72 XP2.6 | SW6.1 45.72,3.56 v43.94,1.78
  Top 0.61: XP2.6 X2.6
  Bottom 0.254: SW15.1 119.38,2.54 93.98,2.54 v93.47,2.03 92.96,2.54 87.63,2.54 86.61,1.52 86.11,1.52 85.09,2.54 69.34,2.54 | 69.34,2.54 62.99,2.54 61.98,1.52 61.47,1.52 60.45,2.54 43.94,2.54 | 43.94,2.54 37.59,2.54 36.58,1.52 36.07,1.52 35.05,2.54 19.05,2.54 v18.54,2.03 | 69.34,2.54 v69.34,2.03 | 43.94,2.54 v43.94,1.78
  Bottom 0.406: X2.6 IC1.26
RB6  (via drill 0.5 pad 1.02)
  Top 0.406: R19.1 13.97,45.97 13.46,45.47 v13.46,41.91
  Top 0.61: XP2.7 X2.7
  Bottom 0.254: IC2.6 5.08,41.66 5.84,42.42 10.92,42.42 11.43,41.91 v13.46,41.91 18.03,41.91 19.81,43.94 21.34,43.94 21.59,43.69 33.02,43.69 33.27,43.94 68.07,43.94 69.85,45.97 XP2.7
  Bottom 0.406: X2.7 IC1.27
RB7  (via drill 0.5 pad 1.02)
  Top 0.254: v17.53,43.18 18.03,42.93 v20.32,42.93
  Top 0.61: XP2.8 X2.8
  Bottom 0.254: IC2.5 2.54,41.91 3.81,43.18 R18.1 v17.53,43.18 | v20.32,42.93 20.57,43.18 33.27,43.18 33.53,43.43 70.36,43.43 72.39,45.72 XP2.8
  Bottom 0.406: X2.8 IC1.28
RC0  (via drill 0.5 pad 1.02)
  Top 0.254: IC1.11 46.99,76.45 47.75,75.44 76.96,75.44 v77.47,76.2
  Top 0.61: X3.1 77.47,48.77 XP3.1
  Bottom 0.254: v77.47,76.2 X3.1 | XP3.1 77.47,47.5 81.28,43.69 97.03,43.69 98.55,45.21 102.11,45.21 R11.1
RC1  (via drill 0.5 pad 1.02)
  Top 0.254: IC1.12 44.45,76.71 46.23,74.93 78.49,74.93 v78.99,75.69
  Top 0.61: X3.2 XP3.2
  Bottom 0.254: v78.99,75.69 78.99,55.88 80.01,54.86 X3.2 | XP3.2 80.01,47.24 83.06,44.2 96.77,44.2 98.3,45.72 105.41,45.72 106.68,44.45 R12.1
RC2  (via drill 0.5 pad 1.02)
  Top 0.254: IC1.13 41.91,76.45 43.69,74.42 80.01,74.42 v80.52,75.18
  Top 0.61: X3.3 XP3.3
  Bottom 0.254: v80.52,75.18 80.52,56.64 82.55,54.61 X3.3 | XP3.3 82.55,47.24 85.09,44.7 96.52,44.7 98.04,46.23 109.98,46.23 110.49,45.72 R13.1
RC3  (via drill 0.5 pad 1.02)
  Top 0.254: IC1.14 39.37,76.2 41.66,73.91 81.53,73.91 v82.04,74.68
  Top 0.61: X3.4 XP3.4
  Bottom 0.254: v82.04,74.68 82.04,57.66 85.09,54.61 X3.4 | XP3.4 85.09,47.24 87.12,45.21 96.27,45.21 97.79,46.74 113.28,46.74 114.3,45.72 R14.1
RC4  (via drill 0.5 pad 1.02)
  Top 0.254: IC1.15 39.37,71.63 41.15,73.41 82.8,73.41 v83.57,74.17
  Top 0.61: X3.5 XP3.5
  Bottom 0.254: v83.57,74.17 83.57,58.93 87.38,54.86 87.63,54.61 X3.5 | XP3.5 87.63,47.24 89.15,45.72 96.01,45.72 97.54,47.24 116.59,47.24 118.11,45.72 R15.1
RC5  (via drill 0.5 pad 1.02)
  Top 0.254: IC1.16 41.91,71.63 43.18,72.9 84.33,72.9 v85.09,73.66
  Top 0.61: X3.6 XP3.6
  Bottom 0.254: v85.09,73.66 85.09,59.94 90.17,54.86 X3.6 | XP3.6 90.17,47.24 91.19,46.23 95.76,46.23 97.28,47.75 119.89,47.75 121.92,45.72 R16.1
RC6  (via drill 0.5 pad 1.02)
  Top 0.254: IC1.17 44.45,68.58 43.69,68.07 33.02,68.07 32.51,67.56 32.51,66.55 | JP2.3 31.24,66.04 31.75,66.55 32.51,66.55 | 32.51,66.55 33.27,66.55 34.29,65.53 v36.83,65.53 | v40.64,91.44 41.15,91.95 56.39,91.95 59.18,89.15 60.2,89.15 61.72,90.68 X5.2
  Bottom 0.254: v36.83,65.53 36.83,67.31 35.56,68.58 35.56,74.93 38.1,77.47 38.1,85.09 40.64,87.63 v40.64,91.44
RC7  (via drill 0.5 pad 1.02)
  Top 0.254: IC1.18 46.99,67.82 45.97,66.8 v35.05,66.8 | JP1.3 34.29,76.2 v36.83,78.74 | v38.1,91.44 39.37,92.71 58.17,92.71 59.44,91.44 X5.1
  Bottom 0.254: v35.05,66.8 34.29,67.56 34.29,77.47 35.56,78.74 v36.83,78.74 36.83,90.17 v38.1,91.44
RX  (via drill 0.5 pad 1.02)
  Top 0.254: JP1.2 34.29,78.74 35.56,80.01 40.13,80.01 v41.66,81.53 | v42.42,86.87 42.42,87.63 45.97,91.19 56.13,91.19 59.69,87.63 59.69,83.06 v60.71,82.04 | v65.28,81.79 65.28,81.53 66.8,80.01 73.66,80.01 v75.69,77.47 | v75.69,56.64 92.96,56.64 95.25,54.36 X3.8
  Top 0.61: X3.8 XP3.8
  Bottom 0.254: v41.66,81.53 41.66,86.11 v42.42,86.87 | v60.71,82.04 65.02,82.04 v65.28,81.79 | v75.69,77.47 75.69,76.2 75.18,75.69 75.18,57.15 v75.69,56.64
TX  (via drill 0.5 pad 1.02)
  Top 0.254: v75.18,54.86 75.69,55.37 91.19,55.37 92.71,53.85 X3.7 | v74.17,77.47 74.17,78.23 73.15,79.5 65.02,79.5 v64.01,80.52 | v58.93,81.53 58.93,87.38 55.88,90.42 46.23,90.42 43.94,88.14 v43.94,84.33 | v43.18,80.01 41.91,80.01 41.15,79.25 38.61,79.25 38.1,78.74 38.1,77.98 36.58,76.45 36.58,71.12 34.8,69.34 32.26,69.34 31.5,68.58 JP2.2
  Top 0.61: X3.7 XP3.7
  Bottom 0.254: v75.18,54.86 73.91,56.13 73.91,76.71 v74.17,77.47 | v64.01,80.52 59.94,80.52 v58.93,81.53 | v43.94,84.33 43.94,80.77 v43.18,80.01
VCC  (via drill 0.5 pad 1.02)
  Top 0.305: IC2.8 10.16,44.45 v11.18,45.72
  Top 0.406: C5.+ 90.17,65.28 90.93,64.52 90.93,60.45 92.46,58.93 97.54,58.93 98.81,60.2 98.81,62.23 97.54,63.5 C4.+ IC6.OUT | C6.+ IC2.8 | T2.E 48.26,39.37 46.99,40.64 XP1.7 | JP3.1 22.1,42.16 25.4,45.47 R17.1
  Top 0.61: v52.07,55.88 48.51,55.88 46.99,54.36 X1.7 XP1.7 | R1.2 R2.2 39.37,86.36 45.72,80.01 60.96,80.01 67.31,86.36 R3.2 | R3.2 X5.4 | R3.2 R4.2 78.74,88.9 82.55,85.09 v82.55,82.55
  Bottom 0.305: XP1.7 46.99,46.99 45.21,45.47 28.19,45.47 27.94,45.72 26.42,45.72 26.16,45.47 20.57,45.47 18.8,47.24 16.26,47.24 14.48,47.24 12.7,47.24 v11.18,45.72
  Bottom 0.406: C5.+ IC1.20 | R5.1 34.29,63.5 38.35,63.5 46.74,55.12 46.74,53.59 X1.7 | T1.E 35.56,38.86 36.83,40.13 42.67,40.13 43.43,39.37 46.99,39.37 T2.E 48.26,38.61 49.78,40.13 55.37,40.13 56.13,39.37 59.69,39.37 T3.E 60.96,38.61 62.48,40.13 68.07,40.13 68.83,39.37 72.14,39.37 T4.E 73.41,38.86 74.68,40.13 80.77,40.13 81.53,39.37 85.09,39.37 T5.E | R17.1 25.4,48.51 24.13,49.78 17.27,49.78 16.26,48.77 16.26,47.24 | 14.48,47.24 R19.2 | IC2.8 R18.2
  Bottom 0.61: v52.07,55.88 C5.+ | v82.55,82.55 82.55,81.28 95.25,68.58 IC6.OUT
(copper drawn outside any net)
  shapes: Top circle x2

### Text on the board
Top: nedoCPU-16 | Register A | A8 | A7 | A6 | A5 | A4 | A3 | A2 | A1 | A0 | D2 | D1 | D0 | W/R | I/M | S/G
Bottom: (C) 2004-2009, Alexander A. Shabarshin (ashabarshin@gmail.com)
tNames: Ternary Legend: | www.3niti.org | 3niti alpha registers: | -1: N (Red/Down) | -4(NN) N: [DPn] | -3(NO) O: [DPo] | 0: O (Off/Center) | -2(NP) P: [DPp] | +1: P (Green/Up) | -1(ON) F: RSF,DPF,BCF | NNN=-13 | PPP=+13 | 0(OO) A: ACCUMULATOR | +1(OP) B: AUX REGISTER | NNO=-12 | PPO=+12 | +2(PN) L: DPx-lower | +3(PO) M: DPx-middle | NNP=-11 | PPN=+11 | PPN=+11 | +4(PP) H: DPx-higher | NON=-10 | POP=+10 | 3niti alpha instruction set: | www.nedoPC.org | NOO=-9 | POO=+9 | SAx (Nxx): save A to x | NOP=-8 | PON=+8 | SPCD (NOO): save PC->DP | RLA (ONN): rot A BCF left | NPN=-7 | PNP=+7 | ADD (ONO): A+B+BCF->A | NPO=-6 | PNO=+6 | RRA (ONP): rot A BCF righ | LAI # (OON): load A from imm | NPP=-5 | PNN=+5 | ADI # (OOO): A+#+BCF->A | ONN=-4 | OPP=+4 | OPA # (OOP): unary function | ONO=-3 | OPO=+3 | LDI ### (OPN): load DP | JMP ### (OPO): load PC | ONP=-2 | OPN=+2 | OPB ### (OPP): binary func | LPCD (POO): load PC from DP | OON=-1 | OOP=+1 | LAx (Pxx): load A from x | OOO=0 | OOO=0 | Rev.B 26-Nov-2009 | 3niti alpha simu1 | Red=-1 Green=+1 | www.3niti.org | A8 | A7 | A6 | A5 | A4 | A3 | A2 | A1 | A0 | D2 | D1 | D0 | W/R | I/M | S/G | www.ternary.info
